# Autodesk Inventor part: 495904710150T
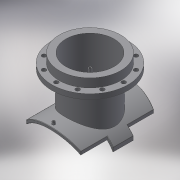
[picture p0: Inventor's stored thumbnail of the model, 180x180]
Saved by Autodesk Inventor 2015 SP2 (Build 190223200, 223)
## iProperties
Created: 2017-10
Part Number: 495904710150T
Material: Generic
Description: PLASSON FLANGED BRANCH SADDLE 450-800X150
Document SubType Name: Modeling
Designer: KIM
Mass: 3163.07 g
Surface Area: 4235.25 cm^2
Volume: 3163.07 cm^3
Density: 1 g/cm^3
Appearance: Default
Author: KIM
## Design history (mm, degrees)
derived "495904.ipt"
feature "Solid1::495904.ipt"
feature "Solid2::495904.ipt"
tag "TaggingFeature1"
body "Solid1"
other parameters: "d1" = 15, "d2" = 283.5, "d4" = 0, "d5" = 315, "d6" = 75, "d7" = 0, "d11" = 4, "d12" = 425.6, "d13" = 14, "d14" = 135, "d16" = 5 deg, "d18" = 4, "d19" = 14, "d20" = 0, "d21" = 3, "d22" = 0, "d23" = 536, "d36" = 135, "d38" = 0, "d39" = 2, "d40" = 121, "d42" = 212, "d43" = 285, "d44" = 96.8, "d46" = 169.6, "d47" = 16, "d48" = 10.4, "d49" = 84.7, "d51" = 816, "d53" = 0, "d54" = 18, "d57" = 0, "d59" = 360 deg, "d61" = 24, "d63" = 0, "d_1" = 212, "B_" = 315, "H_" = 121, "x_" = 15, "D_" = 16, "D_1" = 285, "t_" = 24, "s_" = 18
